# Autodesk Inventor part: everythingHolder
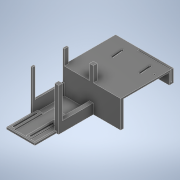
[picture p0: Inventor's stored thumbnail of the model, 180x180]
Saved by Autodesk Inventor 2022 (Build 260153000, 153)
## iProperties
Created: 2022-11
Part Number: everythingHolder
Material: Acetal Resin, Black
Document SubType Name: Modeling
Designer: Wojtus
Density: 1.425 g/cm^3
Appearance: Smooth - Black
Mass: 131.246 g
Surface Area: 567.205 cm^2
Volume: 92.1021 cm^3
Author: Wojtus
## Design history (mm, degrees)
sketch "Sketch2"
  geometry: L1 (38, 103)-(-38, 103); L2 (-38, 103)-(-38, -103); L3 (-38, -103)-(38, -103); L4 (38, -103)-(38, 103); L5 (38, 103)-(-38, -103); L6 (-38, 103)-(38, -103); L7 (90.387, 54.387)-(-14.388, 54.387); L8 (-14.388, 54.387)-(-14.388, 2); L9 (-14.388, 2)-(90.387, 2); L10 (90.387, 2)-(90.387, 54.387); L11 (90.387, 54.387)-(-14.388, 2); L12 (-14.388, 54.387)-(90.387, 2); L13 (38, -3)-(-4.384, -3); L14 (-4.384, -3)-(-4.384, -103); 3 further points
  constraints: 28 end point, 4 parallel, 3 horizontal, 3 perpendicular, 2 midpoint, 2 point on line
  dimensions: "d0" = 76 distance of L3.end L2.end; "d1" = 206 distance of L2.end L1.end; "d2" = 104.775 distance of L9.end L8.end (= 2 x d3); "d3" = 52.3875 distance of L8.end L7.end; "d60" = 105 distance between parallel lines of L9 L3; "d66" = 52.3875 distance between parallel lines of L4 L10 (= d3); "d91" = 5 distance between parallel lines of L9 L13; "d92" = 42.38377 distance between parallel lines of L4 L14
extrude "Extrusion1" new body sketch "Sketch2" stored distance "d4" = 126; taper "d5" = 0 deg
sketch "Sketch4"
  geometry: L1 (3, 3)-(123, 3); L2 (123, 3)-(123, 203); L3 (123, 203)-(3, 203); L4 (3, 203)-(3, 3); L5 (0, 0)-(0, 48.612) reference; L6 (0, 0)-(126, 0) reference; L7 (0, 101)-(0, 206) reference; L8 (126, 206)-(126, 101) reference; L9 (126, 206)-(0, 206) reference; 1 further point
  constraints: 8 end point, 2 parallel, 1 horizontal, 1 perpendicular
  dimensions: "d6" = 120 distance of L3.end L2.end (computed from d40); "d7" = 200 distance of L2.end L1.end (computed from d41); "d8" = 3 distance between parallel lines of L5 L4; "d9" = 3 distance between parallel lines of L6 L1; "d40" = 126 distance between parallel lines of L7 L8 (derived); "d41" = 206 distance between parallel lines of L9 L6 (derived)
extrude "Extrusion2" cut sketch "Sketch4" distance "d10" = 73; taper "d11" = 0 deg
sketch "Sketch5"
  geometry: L1 (3, 3)-(3, 203) reference; L2 (3, 3)-(41, 3); L3 (41, 3)-(41, 53); L4 (41, 53)-(3, 53); L5 (3, 53)-(3, 3); 2 further points
  constraints: 8 end point, 2 parallel, 1 horizontal, 1 perpendicular
  dimensions: "d12" = 38 distance of L4.end L3.end; "d62" = 50 distance between parallel lines of L2 L4
extrude "Extrusion3" join sketch "Sketch5" distance "d13" = 2; taper "d14" = 0 deg
sketch "Sketch6"
  geometry: L1 (41, 3)-(3, 3) reference; L2 (22, 3)-(22, 10.054); L3 (7, 6)-(7, 46.077); L4 (8.6, 6)-(8.6, 46.077); L5 (5.4, 46.077)-(5.4, 6); L6 (3, 3)-(3, 48.612) reference; L7 (37, 6)-(37, 46.077); L8 (35.4, 6)-(35.4, 46.077); L9 (38.6, 46.077)-(38.6, 6); L10 (41, 53)-(3, 53) reference; A1 r 1.6 centre (7, 6) between (5.4, 6) and (8.6, 6); A2 r 1.6 centre (7, 46.077) between (8.6, 46.077) and (5.4, 46.077); A3 r 1.6 centre (37, 6) between (35.4, 6) and (38.6, 6); A4 r 1.6 centre (37, 46.077) between (38.6, 46.077) and (35.4, 46.077); 3 further points
  constraints: 18 end point, 8 point on circle, 7 symmetric about line, 4 centre point, 4 tangent, 2 midpoint, 2 vertical, 1 parallel, 2 other
  dimensions: "d15" = 3.2 diameter of A2; "d17" = 3 distance from line of L1 L3.start; "d18" = 6.92294 distance from line of L10 L3.end; "d63" = 15 distance between parallel lines of L2 L3
extrude "Extrusion4" cut sketch "Sketch6" extent not by distance; stored distance "d19" = 0; taper "d20" = 0 deg
sketch "Sketch7"
  geometry: L1 (11.7, 3)-(32, 3); L2 (32, 3)-(32, 73); L3 (32, 73)-(11.7, 73); L4 (11.7, 73)-(11.7, 3); L5 (11.7, 3)-(32, 73); L6 (32, 3)-(11.7, 73); L7 (123, 3)-(3, 3) reference; L8 (35.4, 6)-(35.4, 46.077) reference; L9 (41, 53)-(3, 53) reference; 2 further points
  constraints: 12 end point, 2 midpoint, 2 parallel, 1 horizontal, 1 perpendicular
  dimensions: "d21" = 20.3 distance of L3.end L2.end; "d22" = 0 distance between parallel lines of L7 L1; "d23" = 3.4 distance between parallel lines of L8 L2 (computed from d15); "d27" = 20 distance between parallel lines of L3 L9
extrude "Extrusion5" cut sketch "Sketch7" distance "d25" = 2.8; taper "d26" = 0 deg
sketch "Sketch8"
  geometry: L1 (11.7, 73)-(32, 73) reference; L2 (21.85, 73)-(21.85, 203); L3 (3, 203)-(123, 203) reference; L4 (29.85, 178)-(31.741, 158); L5 (28.257, 177.849)-(30.148, 157.849); L6 (33.333, 158.151)-(31.443, 178.151); L7 (29.85, 178)-(49.939, 178); L8 (79.85, 178)-(81.741, 158); L9 (78.257, 177.849)-(80.148, 157.849); L10 (83.333, 158.151)-(81.443, 178.151); L11 (79.85, 178)-(99.939, 178); A1 r 1.6 centre (29.85, 178) between (31.443, 178.151) and (28.257, 177.849); A2 r 1.6 centre (31.741, 158) between (30.148, 157.849) and (33.333, 158.151); A3 r 1.6 centre (79.85, 178) between (81.443, 178.151) and (78.257, 177.849); A4 r 1.6 centre (81.741, 158) between (80.148, 157.849) and (83.333, 158.151); 3 further points
  constraints: 22 end point, 8 point on circle, 8 tangent, 4 centre point, 3 midpoint, 2 equal length, 2 horizontal, 2 parallel, 1 point on line, 1 vertical
  dimensions: "d28" = 84.6 deg angle of L4 L7; "d29" = 3.2 diameter of A2; "d30" = 25 distance from line of L3 L4.start; "d31" = 8 distance from line of L2 L4.start; "d32" = 20 vertical distance of L6.start L6.end; "d33" = 84.6 deg angle of L8 L11; "d34" = 3.2 diameter of A4 (= d29); "d35" = 25 distance from line of L3 L8.start (= d30); "d36" = 50 distance of L4.start L8.start; "d37" = 20 vertical distance of L10.start L10.end
extrude "Extrusion6" cut sketch "Sketch8" extent not by distance; stored distance "d38" = 0; taper "d39" = 0 deg
sketch "Sketch9"
  geometry: L1 (48, 38.612)-(55, 38.612); L2 (55, 38.612)-(55, 108.462); L3 (55, 108.462)-(48, 108.462); L4 (48, 108.462)-(48, 38.612); L5 (3, 101)-(3, 203) reference; L6 (123, 3)-(3, 3) reference; L7 (123, 48.612)-(123, 3) reference; L8 (123, 3)-(3, 3) reference; L9 (3, 3)-(3, 48.612) reference; L10 (0, 48.612)-(3, 48.612) reference; L11 (0, 0)-(0, 48.612) reference; L12 (0, 0)-(126, 0) reference; L13 (126, 48.612)-(126, 0) reference; L14 (123, 48.612)-(126, 48.612) reference; L15 (0, 101)-(3, 101) reference; 1 further point
  constraints: 8 end point, 2 parallel, 1 horizontal, 1 perpendicular
  dimensions: "d42" = 45 distance between parallel lines of L5 L4; "d43" = 35.6125 distance between parallel lines of L6 L1 (computed from d61); "d44" = 69.85 distance between parallel lines of L3 L1 (= 1.33333 x d67); "d45" = 7 distance between parallel lines of L4 L2; "d61" = 45.6125 distance between parallel lines of L8 L10 (derived); "d67" = 52.3875 distance between parallel lines of L15 L10 (derived)
extrude "Extrusion7" join sketch "Sketch9" distance "d46" = 15; taper "d47" = 0 deg
sketch "Sketch10"
  geometry: L1 (79.85, 178)-(96.561, 178); L2 (96.561, 178)-(96.561, 169.074); L3 (29.85, 178)-(29.85, 106.898); L4 (29.85, 106.898)-(44.35, 106.898); C1 r 1.5 at (96.561, 169.074); C2 r 1.5 at (44.35, 106.898); A1 r 1.6 centre (79.85, 178) between (81.443, 178.151) and (78.257, 177.849) reference; A2 r 1.6 centre (31.741, 158) between (30.148, 157.849) and (33.333, 158.151) reference; A3 r 1.6 centre (29.85, 178) between (31.443, 178.151) and (28.257, 177.849) reference; 1 further point
  constraints: 8 end point, 2 centre point, 2 horizontal, 2 vertical, 1 coincident
  dimensions: "d50" = 16.711 distance of L1.start L1.end; "d51" = 8.926 distance of L1.end L2.end; "d52" = 3 diameter of C1; "d55" = 3 diameter of C2; "d64" = 71.102 distance of L3.start L3.end; "d65" = 14.5 distance of L3.end L4.end
extrude "Extrusion8" cut sketch "Sketch10" distance "d56" = 15; taper "d57" = 0 deg
sketch "Sketch11"
  geometry: L1 (3, 101)-(3, 203) reference; L2 (3, 101)-(103.99, 101); L3 (103.99, 101)-(103.99, 203); L4 (3, 203)-(123, 203) reference; L5 (30.148, 157.849)-(28.257, 177.849) reference; L6 (31.443, 178.151)-(33.333, 158.151) reference; L7 (80.148, 157.849)-(78.257, 177.849) reference; L8 (81.443, 178.151)-(83.333, 158.151) reference; C1 r 1.5 at (44.35, 106.898) reference; C2 r 1.5 at (96.561, 169.074) reference; A1 r 1.6 centre (31.741, 158) between (30.148, 157.849) and (33.333, 158.151) reference; A2 r 1.6 centre (29.85, 178) between (31.443, 178.151) and (28.257, 177.849) reference; A3 r 1.6 centre (79.85, 178) between (81.443, 178.151) and (78.257, 177.849) reference; A4 r 1.6 centre (81.741, 158) between (80.148, 157.849) and (83.333, 158.151) reference; 1 further point
  constraints: 4 end point, 1 horizontal, 1 perpendicular, 1 point on line
  dimensions: "d70" = 100.99016 distance of L1.start L2.end
extrude "Extrusion9" join sketch "Sketch11" distance "d68" = 46.25; taper "d69" = 0 deg
sketch "Sketch12"
  geometry: L1 (55, 101)-(48, 101) reference; L2 (55, 101)-(48, 101); L3 (48, 101)-(48, 108); L4 (48, 108)-(55, 108); L5 (55, 108)-(55, 101); L6 (123, 3)-(41, 3) reference; L7 (48, 38.612)-(55, 38.612) reference; L8 (48, 3)-(51, 3); L9 (51, 3)-(51, 38.612); L10 (51, 38.612)-(48, 38.612); L11 (48, 38.612)-(48, 3); 4 further points
  constraints: 16 end point, 4 parallel, 2 horizontal, 2 perpendicular, 2 point on line
  dimensions: "d71" = 7 distance of L2.end L3.end; "d72" = 3 distance of L10.end L9.end
extrude "Extrusion10" join sketch "Sketch12" distance "d73" = 47.25; taper "d74" = 0 deg
extrude "Extrusion11" join sketch "Sketch12" distance "d75" = 26.75; taper "d76" = 0 deg
sketch "Sketch13"
  geometry: L1 (51, 38.612)-(51, 3) reference; L2 (123, 3)-(51, 3) reference; L3 (123, 203)-(123, 3) reference; L4 (103.99, 203)-(123, 203) reference; L5 (103.99, 203)-(103.99, 101) reference; L6 (103.99, 101)-(55, 101) reference; L7 (55, 101)-(55, 38.612) reference; L8 (55, 38.612)-(51, 38.612) reference; L9 (126, 206)-(0, 206) reference; L10 (103.99, 206)-(103.99, 101); L11 (103.99, 101)-(55, 101) reference; L12 (55, 101)-(55, 38.612) reference; L13 (55, 101)-(55, 38.612); L14 (51, 38.612)-(51, 0); L15 (0, 0)-(126, 0) reference; L16 (126, 0)-(126, 206); L17 (126, 206)-(126, 101) reference; L18 (126, 206)-(103.99, 206); L19 (51, 0)-(126, 0); L20 (51, 38.612)-(55, 38.612); 3 further points
  constraints: 14 end point, 2 collinear, 2 parallel, 2 point on line, 2 vertical, 1 horizontal
extrude "Extrusion12" cut sketch "Sketch13" stored distance "d77" = 268.5; taper "d78" = 0 deg
sketch "Sketch14"
  geometry: L1 (103.99, 206)-(103.99, 101) reference; L2 (103.99, 193)-(43.99, 193); L3 (43.99, 193)-(43.99, 191.412); L4 (43.99, 191.412)-(103.99, 191.412); L5 (103.99, 191.412)-(103.99, 193); L6 (3, 203)-(103.99, 203) reference; 2 further points
  constraints: 8 end point, 2 parallel, 1 horizontal, 1 perpendicular, 1 point on line
  dimensions: "d79" = 60 distance of L4.end L3.end; "d80" = 1.5875 distance of L3.end L2.end; "d81" = 10 distance between parallel lines of L6 L2
extrude "Extrusion13" cut sketch "Sketch14" distance "d82" = 20; taper "d83" = 0 deg
sketch "Sketch15"
  geometry: L1 (0, 0)-(-206, 0) reference; L2 (-100, 0)-(-17.588, 0); L3 (-17.588, 26.25)-(-17.588, 46.25); L4 (-17.588, 46.25)-(-100, 46.25); L5 (-100, 46.25)-(-100, 0); L6 (-105, 0)-(-105, 49.25) reference; L7 (-105, 49.25)-(-14.588, 49.25) reference; L8 (-14.588, 29.25)-(-14.588, 49.25) reference; L9 (-17.588, 26.25)-(-10, 26.25); L10 (-10, 26.25)-(-10, 49.25); L11 (-13, 49.25)-(-3, 49.25) reference; L12 (-13, 49.25)-(-13, 29.25) reference; L13 (-10, 49.25)-(0, 49.25); L14 (0, 76)-(0, 0) reference; L15 (0, 0)-(-105, 0) reference; L16 (0, 49.25)-(0, 0); L17 (0, 0)-(-17.588, 0); 2 further points
  constraints: 18 end point, 3 horizontal, 3 point on line, 2 parallel, 2 perpendicular, 1 collinear, 1 vertical
  dimensions: "d84" = 5 distance between parallel lines of L6 L5; "d85" = 3 distance between parallel lines of L7 L4; "d86" = 3 distance between parallel lines of L8 L3; "d87" = 3 distance between parallel lines of L10 L12; "d88" = 3 distance from line of L12.end L9
extrude "Extrusion14" cut sketch "Sketch15" extent not by distance; stored distance "d89" = 0; taper "d90" = 0 deg
sketch "Sketch16"
  geometry: L1 (0, 0)-(102, 0) reference; L2 (105, 0)-(105, -26.75) reference; L3 (7.129, 0)-(105, 0); L4 (105, 0)-(105, -26.75); L5 (105, -26.75)-(7.129, -26.75); L6 (7.129, -26.75)-(7.129, 0); 3 further points
  constraints: 8 end point, 2 parallel, 1 horizontal, 1 perpendicular, 1 point on line
extrude "Extrusion15" cut sketch "Sketch16" stored distance "d93" = 654.25; taper "d94" = 0 deg
sketch "Sketch18"
  geometry: L1 (0, 0)-(103.99, 0) reference; L2 (60.842, 20)-(103.99, 20) reference; L3 (103.99, 0)-(63, 0); L4 (63, 0)-(63, 20); L5 (63, 20)-(103.99, 20); L6 (103.99, 20)-(103.99, 0); L7 (60, 23)-(0, 23) reference; L8 (60, 23)-(60, 3) reference; 3 further points
  constraints: 8 end point, 2 parallel, 1 horizontal, 1 perpendicular, 1 point on line
  dimensions: "d97" = 3 distance between parallel lines of L4 L8
extrude "Extrusion17" cut sketch "Sketch18" distance "d98" = 10; taper "d99" = 0 deg
sketch "Sketch20"
  geometry: L1 (55, 38.612)-(55, 101) reference; L2 (55, 38.612)-(48, 38.612); L3 (48, 38.612)-(48, 45.612); L4 (48, 45.612)-(55, 45.612); L5 (55, 45.612)-(55, 38.612); L6 (0, 48.612)-(3, 48.612) reference; L7 (48, 101)-(48, 38.612) reference; 2 further points
  constraints: 8 end point, 2 parallel, 1 horizontal, 1 perpendicular
  dimensions: "d100" = 3 distance between parallel lines of L4 L6; "d106" = 0 distance between parallel lines of L7 L3
extrude "Extrusion18" join sketch "Sketch20" distance "d101" = 58.25; taper "d102" = 0 deg
sketch "Sketch21"
  geometry: L1 (3, 3)-(3, 53) reference; L2 (3, 43.612)-(0, 43.612); L3 (0, 106)-(0, 0) reference; L4 (0, 48.612)-(3, 48.612) reference; L5 (0, 43.612)-(0, 0); L6 (0, 0)-(51, 0) reference; L7 (0, 0)-(51, 0); L8 (51, 0)-(51, 38.612) reference; L9 (51, 0)-(51, 38.612); L10 (48, 101)-(48, 38.612) reference; L11 (51, 38.612)-(48, 38.612); L12 (48, 3)-(48, 101) reference; L13 (48, 38.612)-(48, 3); L14 (11.7, 3)-(3, 3) reference; L15 (48, 3)-(3, 3); L16 (3, 3)-(3, 43.612); 2 further points
  constraints: 16 end point, 5 collinear, 2 perpendicular, 2 point on line, 1 horizontal
  dimensions: "d103" = 5 distance between parallel lines of L2 L4
extrude "Extrusion19" cut sketch "Sketch21" distance "d104" = 72.5; taper "d105" = 0 deg
body "Solid1"
node "Projected Loop1"
node "Projected Loop2"
other parameters: "sa_0" = 4
